(* Logix 5000 project; controller ControlLogix 1756-L63 rev 18.11; software revision 18.01 *)

TASK MainTask (continuous, watchdog 500 ms) : MainProgram

MODULES
   Local : 1756-L63 (ICP 0, rev 18.11)
      Local_ENBT : 1756-ENBT (ICP 3, Ethernet 105.102.0.155, rev 2.4)
         Remote_ENBT : 1756-ENBT (Ethernet 105.102.0.65, rev 1.1, Output RPI 20 ms)
            MCMR : vendor 1 type 0 code 15 (ICP 1, rev 1.1, Output RPI 5 ms)
END_MODULES

TYPE MCMRBlockStats :   // This object is used to store the block transfer statistics for the module.
STRUCT
   Read : INT;   // Total number of read block transfers
   Write : INT;   // Total number of write block transfers
   Parse : INT;   // Total number of blocks parsed
   Event : INT;   // Total number of event blocks received
   Cmd : INT;   // Total number of command blocks received
   Err : INT;   // Total number of block transfer errors
END_STRUCT
END_TYPE

TYPE MCMRCmdControl :   // Tags for command control
STRUCT
   CmdTrigger : BOOL;   // Command Trigger
   CmdControlData : INT[21];   // Command Control Data
   CmdControlResp : INT[5];   // Command Control Response
   CmdErrTrigger : BOOL;   // Command Error Trigger
   CmdErrData : INT[102];   // Command Error Data
END_STRUCT
END_TYPE

TYPE MCMRCONTROL :   // Tags used for special blocks
STRUCT
   ColdBoot : BOOL;   // Cold Boot
   WarmBoot : BOOL;   // Warm Boot
   CmdControlP1 : MCMRCmdControl;   // Command Control for Port 1
   CmdControlP2 : MCMRCmdControl;   // Command Control for Port 2
   EventTriggerP1 : BOOL;   // Triggers the Event Command.
   EventTriggerP2 : BOOL;   // Triggers the Event Command.
   EventCmdP1 : MCMREventCmd[100];   // Event Command for Port 1
   EventCmdP2 : MCMREventCmd[100];   // Event Command for Port 2
   EventCmdRespP1 : INT[5];   // Event Command Response for Port 1
   EventCmdRespP2 : INT[5];   // Event Command Response for Port 2
END_STRUCT
END_TYPE

TYPE MCMRDATA :   // This object contains the Read & Write Data Arrays.
STRUCT
   ReadData : INT[600];   // Data read from module
   WriteData : INT[600];   // Data to write to module
END_STRUCT
END_TYPE

TYPE MCMREventCmd :   // This object is used to contain the attributes to define a master command. An array of these objects is used for each port.
STRUCT
   Enable : INT;   // 0=Disable,1=Continuous,2=Event Command
   IntAddress : INT;   // Module's internal address associated with the command
   PollInt : INT;   // Minimum number of seconds between issuance of command (0-65535 Sec)
   Count : INT;   // Number of registers associated with the command
   Swap : INT;   // Swap code used with command
   Device : INT;   // Device index in Device Table to associate with the command
   Func : INT;   // Function code for the command
   DevAddress : INT;   // Address in device associated with the command
END_STRUCT
END_TYPE

TYPE MCMRInitOutputData :   // Used to bring the Module into a known state after a restart operation.
STRUCT
   InitOutBlkIDLim : INT;   // Block Index Limit for ReadData size of the array
END_STRUCT
END_TYPE

TYPE MCMRModuleDef :   // This object contains variables to be used with the module and status data related to the module.
STRUCT
   DATA : MCMRDATA;   // Read Data and Write Data
   STATUS : MCMRSTATUS;   // Status information in each read block
   CONTROL : MCMRCONTROL;   // Command Control Object
   UTIL : MCMRUTIL;   // Backplane Object
END_STRUCT
END_TYPE

TYPE MCMRPortStats :   // This object is used to store the port statistics
STRUCT
   PortTrigger : BOOL;   // Triggers port status reading
   CmdReq : INT;   // Total number of command list requests sent
   CmdResp : INT;   // Total number of command list responses received
   CmdErr : INT;   // Total number of command list errors
   Requests : INT;   // Total number of requests for port
   Responses : INT;   // Total number of responses for port
   ErrSent : INT;   // Total number of errors sent
   ErrRec : INT;   // Total number of errors received
   SlaveStats : SINT[250];   // Port Slave status values
END_STRUCT
END_TYPE

TYPE MCMRSTATUS :   // This status data is returned on each read block and can be used to detect proper module operation.
STRUCT
   PassCnt : INT;   // Program cycle counter
   Product : INT[2];   // Product Name
   Rev : INT[2];   // Revision Level Number
   OP : INT[2];   // Operating Level Number
   Run : INT[2];   // Run Number
   Port1Stats : MCMRPortStats;   // Port error statistics for Port 1
   Port2Stats : MCMRPortStats;   // Port error statistics for Port 2
   Block : MCMRBlockStats;   // Block transfer statistics
   Port1CurrentErr : INT;   // Current error/index for Port 1
   Port1LastErr : INT;   // Last error/index for Port 1
   Port2CurrentErr : INT;   // Current error/index for Port 2
   Port2LastErr : INT;   // Last error/index for Port 2
   StatusMsgData : INT[46];   // Triggers status message data
   StatusTrigger : BOOL;   // Triggers Status reading.
END_STRUCT
END_TYPE

TYPE MCMRUTIL :   // This object stores all the variables required for data transfer operation between the module and the controller.
STRUCT
   LastRead : INT;   // Index of last read block
   LastWrite : INT;   // Index of last write block
   BlockIndex : INT;   // Computed block offset for data table
   ReadDataSize : DINT;   // Size of Read Data Array
   WriteDataSize : DINT;   // Size of Write Data Array
   RBTSremainder : INT;   // Computed remainder from Read Data Array size
   WBTSremainder : INT;   // Computed remainder from Write Data Array size
   MaxReadBlock : DINT;   // Maximum read block
   MaxWriteBlock : DINT;   // Maximum write block
   InitOutputData : MCMRInitOutputData;   // This is to initialize output data module reads data from PLC
END_STRUCT
END_TYPE

ADD_ON_INSTRUCTION AOI56MCMR   (* revision 1.5, vendor ProSoft Technology Inc., ExecutePrescan *)
// Add-On - MVI56-MCMR & MVI56E-MCMR modules.
// Revision note:
// v1.5 - Initialize output data block now flexible to accommodate for flexible read and write data arrays.
VAR_IN_OUT
   Connection_Input : INT[42]; {required}   // Input parameters.
   Connection_Output : INT[42]; {required}   // Output parameters.
   MCMR : MCMRModuleDef; {required}
   CmdControlP1_MSG : MESSAGE; {required}
   CmdControlP2_MSG : MESSAGE; {required}
   CmdControlRespP1_MSG : MESSAGE; {required}
   CmdControlRespP2_MSG : MESSAGE; {required}
   CmdErrorP1_MSG : MESSAGE; {required}
   CmdErrorP2_MSG : MESSAGE; {required}
   EventCmdP1_MSG : MESSAGE; {required}
   EventCmdP2_MSG : MESSAGE; {required}
   EventCmdRespP1_MSG : MESSAGE; {required}
   EventCmdRespP2_MSG : MESSAGE; {required}
   SlaveStatusP1_MSG : MESSAGE; {required}
   SlaveStatusP2_MSG : MESSAGE; {required}
   ModuleStatus_MSG : MESSAGE; {required}
END_VAR
VAR
   MJFAULTS : DINT[12];
END_VAR

ROUTINE Logic   (* ladder *)
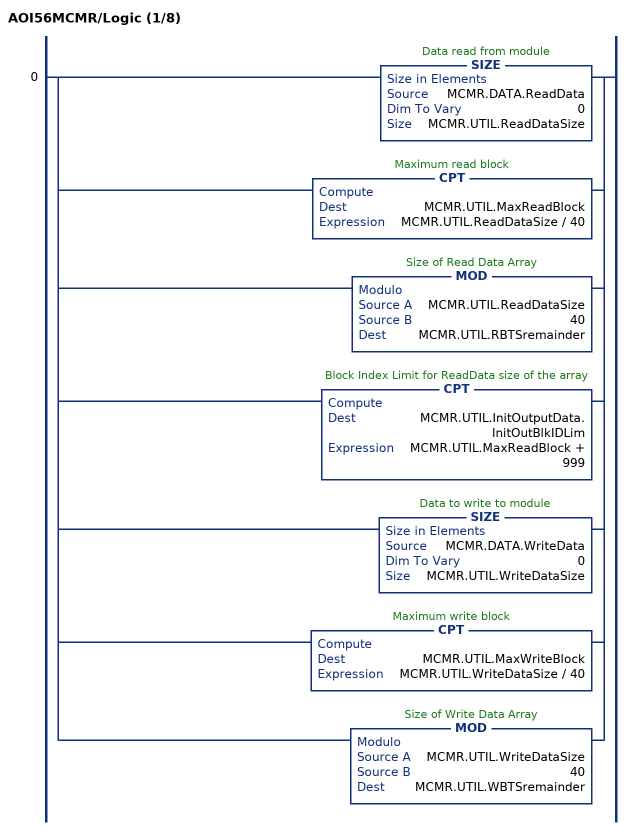
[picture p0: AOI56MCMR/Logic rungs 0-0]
   0: [SIZE(MCMR.DATA.ReadData,0,MCMR.UTIL.ReadDataSize) ,CPT(MCMR.UTIL.MaxReadBlock,MCMR.UTIL.ReadDataSize / 40) ,MOD(MCMR.UTIL.ReadDataSize,40,MCMR.UTIL.RBTSremainder) ,CPT(MCMR.UTIL.InitOutputData.InitOutBlkIDLim,MCMR.UTIL.MaxReadBlock + 999) ,SIZE(MCMR.DATA.WriteData,0,MCMR.UTIL.WriteDataSize) ,CPT(MCMR.UTIL.MaxWriteBlock,MCMR.UTIL.WriteDataSize / 40) ,MOD(MCMR.UTIL.WriteDataSize,40,MCMR.UTIL.WBTSremainder) ];
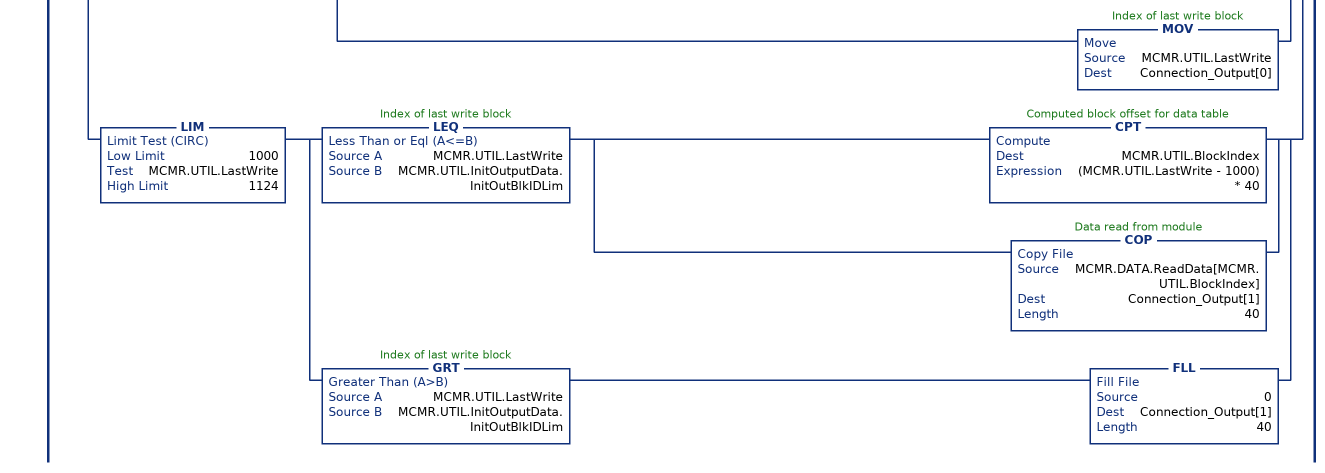
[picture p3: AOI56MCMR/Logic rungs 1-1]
   // This rung is used to check for a new read block from the MVI56-MBP module in slot 1.  If new data is available, the LastRead and word[0] will not be equal.  This will force the program to call the ReadData subroutine to process the new data received.  After the new data is placed in the Modbus Data Table, the program will send new data to the module using the WriteData subroutine.
   1: NEQ(Connection_Input[41],MCMR.UTIL.LastRead)[MOV(Connection_Input[41],MCMR.UTIL.LastRead) ,GEQ(MCMR.UTIL.LastRead,1) [LEQ(MCMR.UTIL.LastRead,MCMR.UTIL.MaxReadBlock) [CPT(MCMR.UTIL.BlockIndex,(MCMR.UTIL.LastRead - 1) * 40) ,COP(Connection_Input[1],MCMR.DATA.ReadData[MCMR.UTIL.BlockIndex],40) ] ,CMP(MCMR.UTIL.LastRead - MCMR.UTIL.MaxReadBlock = 1) GRT(MCMR.UTIL.RBTSremainder,0) [CPT(MCMR.UTIL.BlockIndex,(MCMR.UTIL.LastRead - 1) * 40) ,COP(Connection_Input[1],MCMR.DATA.ReadData[MCMR.UTIL.BlockIndex],MCMR.UTIL.RBTSremainder) ] ] ,MOV(Connection_Input[0],MCMR.UTIL.LastWrite) ,XIC(MCMR.CONTROL.WarmBoot) [MOV(9998,MCMR.UTIL.LastWrite) ,MOV(9998,Connection_Output[0]) ,OTU(MCMR.CONTROL.WarmBoot) ] ,XIC(MCMR.CONTROL.ColdBoot) [MOV(9999,MCMR.UTIL.LastWrite) ,MOV(9999,Connection_Output[0]) ,OTU(MCMR.CONTROL.ColdBoot) ] ,[EQU(-1,MCMR.UTIL.LastWrite) ,EQU(0,MCMR.UTIL.LastWrite) ] MOV(MCMR.UTIL.LastWrite,Connection_Output[0]) ,GEQ(MCMR.UTIL.LastWrite,1) [LEQ(MCMR.UTIL.LastWrite,MCMR.UTIL.MaxWriteBlock) [CPT(MCMR.UTIL.BlockIndex,(MCMR.UTIL.LastWrite - 1) * 40) ,COP(MCMR.DATA.WriteData[MCMR.UTIL.BlockIndex],Connection_Output[1],40) ] ,CMP(MCMR.UTIL.LastWrite - MCMR.UTIL.MaxWriteBlock = 1) GRT(MCMR.UTIL.WBTSremainder,0) [CPT(MCMR.UTIL.BlockIndex,(MCMR.UTIL.LastWrite - 1) * 40) ,COP(MCMR.DATA.WriteData[MCMR.UTIL.BlockIndex],Connection_Output[1],MCMR.UTIL.WBTSremainder) ] ,MOV(MCMR.UTIL.LastWrite,Connection_Output[0]) ] ,LIM(1000,MCMR.UTIL.LastWrite,1124) [LEQ(MCMR.UTIL.LastWrite,MCMR.UTIL.InitOutputData.InitOutBlkIDLim) [CPT(MCMR.UTIL.BlockIndex,(MCMR.UTIL.LastWrite - 1000) * 40) ,COP(MCMR.DATA.ReadData[MCMR.UTIL.BlockIndex],Connection_Output[1],40) ] ,GRT(MCMR.UTIL.LastWrite,MCMR.UTIL.InitOutputData.InitOutBlkIDLim) FLL(0,Connection_Output[1],40) ] ];
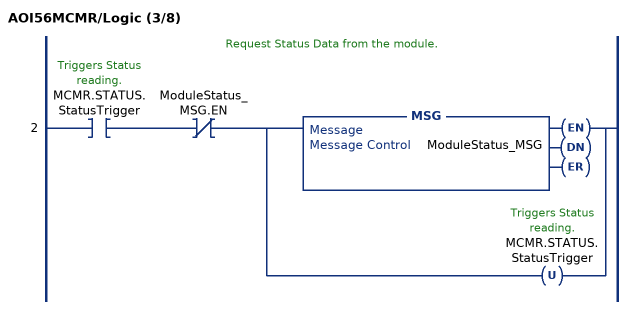
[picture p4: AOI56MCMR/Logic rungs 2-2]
   // Request Status Data from the module.
   2: XIC(MCMR.STATUS.StatusTrigger)XIO(ModuleStatus_MSG.EN)[MSG(ModuleStatus_MSG) ,OTU(MCMR.STATUS.StatusTrigger) ];
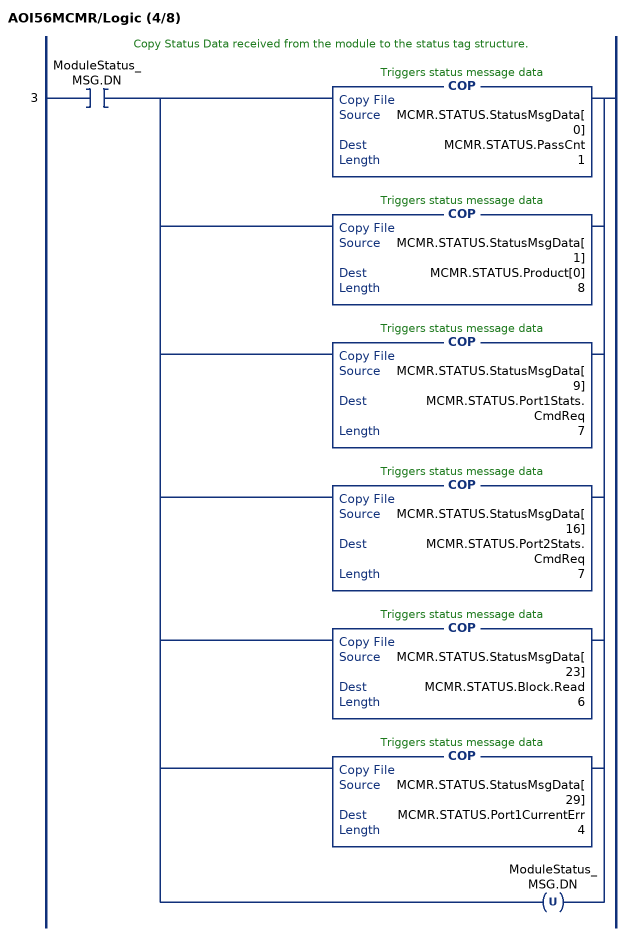
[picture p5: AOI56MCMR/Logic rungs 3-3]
   // Copy Status Data received from the module to the status tag structure.
   3: XIC(ModuleStatus_MSG.DN)[COP(MCMR.STATUS.StatusMsgData[0],MCMR.STATUS.PassCnt,1) ,COP(MCMR.STATUS.StatusMsgData[1],MCMR.STATUS.Product[0],8) ,COP(MCMR.STATUS.StatusMsgData[9],MCMR.STATUS.Port1Stats.CmdReq,7) ,COP(MCMR.STATUS.StatusMsgData[16],MCMR.STATUS.Port2Stats.CmdReq,7) ,COP(MCMR.STATUS.StatusMsgData[23],MCMR.STATUS.Block.Read,6) ,COP(MCMR.STATUS.StatusMsgData[29],MCMR.STATUS.Port1CurrentErr,4) ,OTU(ModuleStatus_MSG.DN) ];
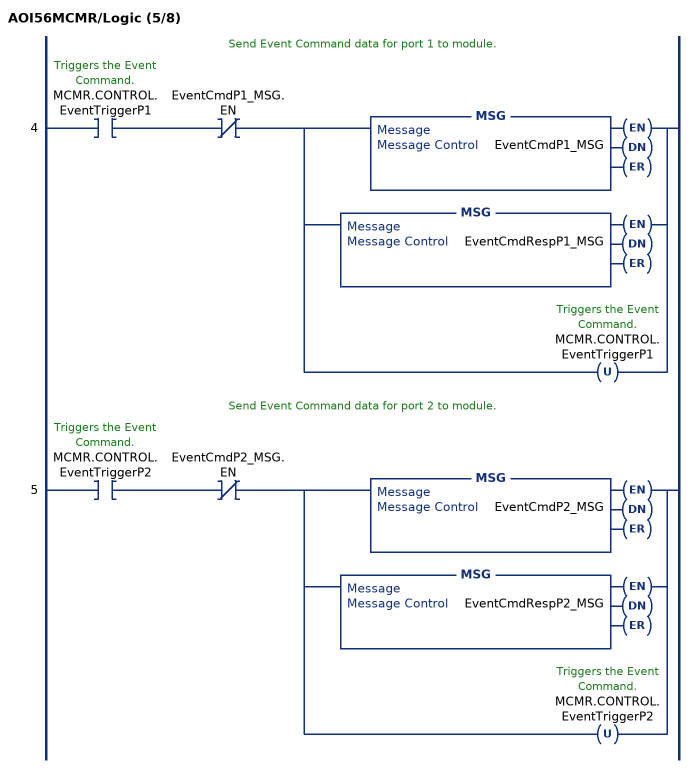
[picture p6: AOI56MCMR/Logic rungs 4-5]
   // Send Event Command data for port 1 to module.
   4: XIC(MCMR.CONTROL.EventTriggerP1)XIO(EventCmdP1_MSG.EN)[[MSG(EventCmdP1_MSG) ,MSG(EventCmdRespP1_MSG) ] ,OTU(MCMR.CONTROL.EventTriggerP1) ];
   // Send Event Command data for port 2 to module.
   5: XIC(MCMR.CONTROL.EventTriggerP2)XIO(EventCmdP2_MSG.EN)[[MSG(EventCmdP2_MSG) ,MSG(EventCmdRespP2_MSG) ] ,OTU(MCMR.CONTROL.EventTriggerP2) ];
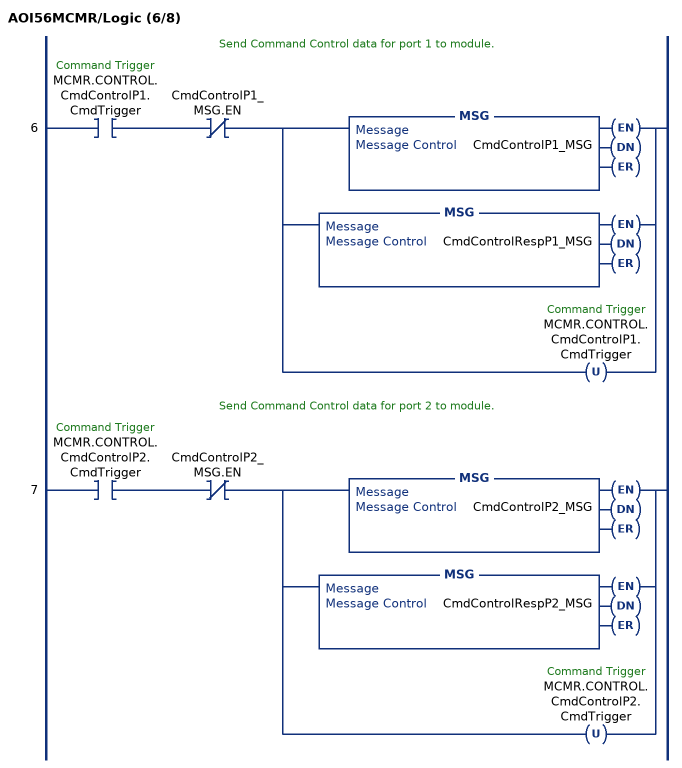
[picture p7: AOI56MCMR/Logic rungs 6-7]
   // Send Command Control data for port 1 to module.
   6: XIC(MCMR.CONTROL.CmdControlP1.CmdTrigger)XIO(CmdControlP1_MSG.EN)[[MSG(CmdControlP1_MSG) ,MSG(CmdControlRespP1_MSG) ] ,OTU(MCMR.CONTROL.CmdControlP1.CmdTrigger) ];
   // Send Command Control data for port 2 to module.
   7: XIC(MCMR.CONTROL.CmdControlP2.CmdTrigger)XIO(CmdControlP2_MSG.EN)[[MSG(CmdControlP2_MSG) ,MSG(CmdControlRespP2_MSG) ] ,OTU(MCMR.CONTROL.CmdControlP2.CmdTrigger) ];
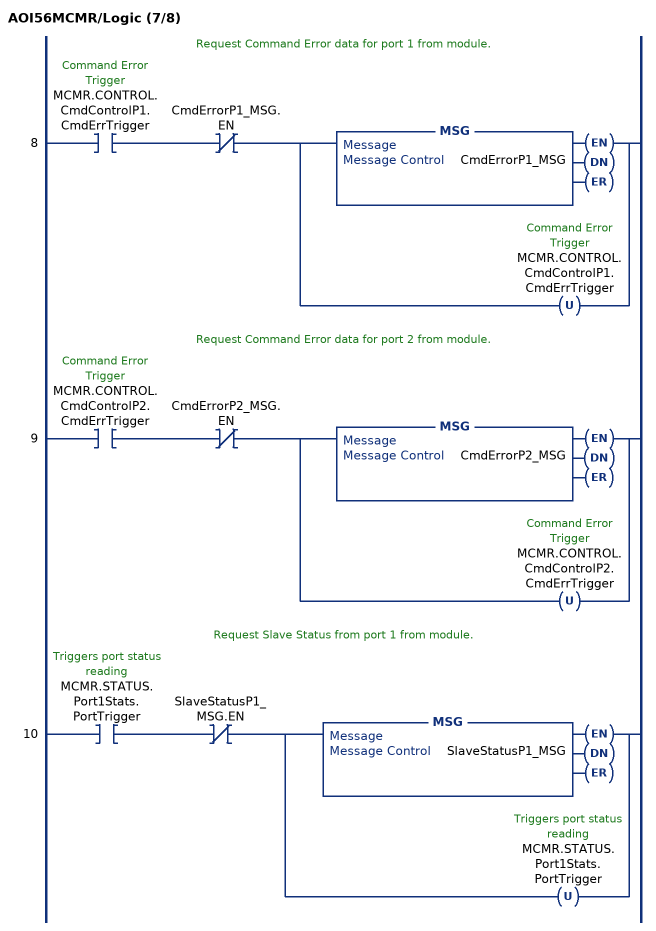
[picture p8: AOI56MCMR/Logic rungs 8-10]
   // Request Command Error data for port 1 from module.
   8: XIC(MCMR.CONTROL.CmdControlP1.CmdErrTrigger)XIO(CmdErrorP1_MSG.EN)[MSG(CmdErrorP1_MSG) ,OTU(MCMR.CONTROL.CmdControlP1.CmdErrTrigger) ];
   // Request Command Error data for port 2 from module.
   9: XIC(MCMR.CONTROL.CmdControlP2.CmdErrTrigger)XIO(CmdErrorP2_MSG.EN)[MSG(CmdErrorP2_MSG) ,OTU(MCMR.CONTROL.CmdControlP2.CmdErrTrigger) ];
   // Request Slave Status from port 1 from module.
   10: XIC(MCMR.STATUS.Port1Stats.PortTrigger)XIO(SlaveStatusP1_MSG.EN)[MSG(SlaveStatusP1_MSG) ,OTU(MCMR.STATUS.Port1Stats.PortTrigger) ];
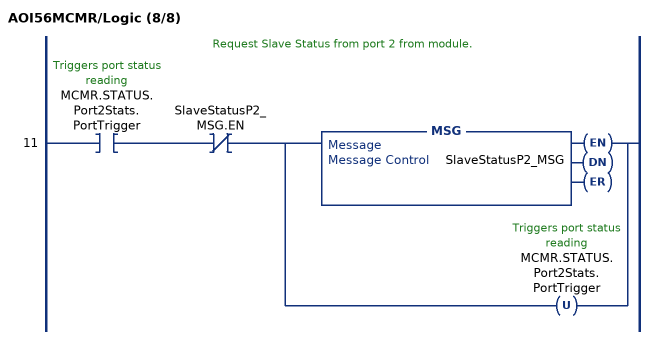
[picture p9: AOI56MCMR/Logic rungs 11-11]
   // Request Slave Status from port 2 from module.
   11: XIC(MCMR.STATUS.Port2Stats.PortTrigger)XIO(SlaveStatusP2_MSG.EN)[MSG(SlaveStatusP2_MSG) ,OTU(MCMR.STATUS.Port2Stats.PortTrigger) ];
END_ROUTINE

ROUTINE Prescan   (* ladder *)
// Startup
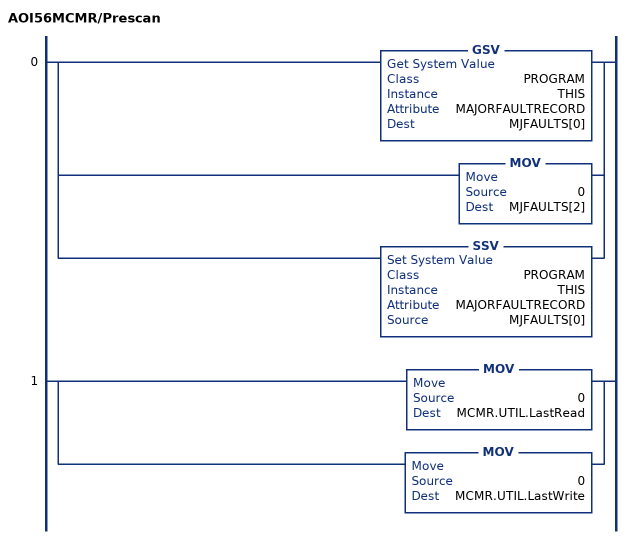
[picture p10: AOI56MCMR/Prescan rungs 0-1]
   0: [GSV(PROGRAM,THIS,MAJORFAULTRECORD,MJFAULTS[0]) ,MOV(0,MJFAULTS[2]) ,SSV(PROGRAM,THIS,MAJORFAULTRECORD,MJFAULTS[0]) ];
   1: [MOV(0,MCMR.UTIL.LastRead) ,MOV(0,MCMR.UTIL.LastWrite) ];
END_ROUTINE
END_ADD_ON_INSTRUCTION

VAR_GLOBAL   (* controller tags *)
   AOI56MCMR : AOI56MCMR;
   CmdControlP1_MSG : MESSAGE;
        MessageParameters(ServiceCode := 16#0010, LocalElement := MCMR.CONTROL.CmdControlP1.CmdControlData[0], ...)
   CmdControlP2_MSG : MESSAGE;
        MessageParameters(ServiceCode := 16#0010, LocalElement := MCMR.CONTROL.CmdControlP2.CmdControlData[0], ...)
   CmdControlRespP1_MSG : MESSAGE;
        MessageParameters(ServiceCode := 16#000e, DestinationTag := MCMR.CONTROL.CmdControlP1.CmdControlResp[0], ...)
   CmdControlRespP2_MSG : MESSAGE;
        MessageParameters(ServiceCode := 16#000e, DestinationTag := MCMR.CONTROL.CmdControlP2.CmdControlResp[0], ...)
   CmdErrorP1_MSG : MESSAGE;
        MessageParameters(ServiceCode := 16#000e, DestinationTag := MCMR.CONTROL.CmdControlP1.CmdErrData[0], ...)
   CmdErrorP2_MSG : MESSAGE;
        MessageParameters(ServiceCode := 16#000e, DestinationTag := MCMR.CONTROL.CmdControlP2.CmdErrData[0], ...)
   EventCmdP1_MSG : MESSAGE;
        MessageParameters(ServiceCode := 16#0010, LocalElement := MCMR.CONTROL.EventCmdP1[0], ...)
   EventCmdP2_MSG : MESSAGE;
        MessageParameters(ServiceCode := 16#0010, LocalElement := MCMR.CONTROL.EventCmdP2[0], ...)
   EventCmdRespP1_MSG : MESSAGE;
        MessageParameters(ServiceCode := 16#000e, DestinationTag := MCMR.CONTROL.EventCmdRespP1[0], ...)
   EventCmdRespP2_MSG : MESSAGE;
        MessageParameters(ServiceCode := 16#000e, DestinationTag := MCMR.CONTROL.EventCmdRespP2[0], ...)
   MCMR : MCMRModuleDef;
   ModuleStatus_MSG : MESSAGE;
        MessageParameters(ServiceCode := 16#000e, DestinationTag := MCMR.STATUS.StatusMsgData[0], ...)
   SlaveStatusP1_MSG : MESSAGE;
        MessageParameters(ServiceCode := 16#000e, DestinationTag := MCMR.STATUS.Port1Stats.SlaveStats[0], ...)
   SlaveStatusP2_MSG : MESSAGE;
        MessageParameters(ServiceCode := 16#000e, DestinationTag := MCMR.STATUS.Port2Stats.SlaveStats[0], ...)
END_VAR

PROGRAM MainProgram   (* main routine MainRoutine *)

ROUTINE MainRoutine   (* ladder *)
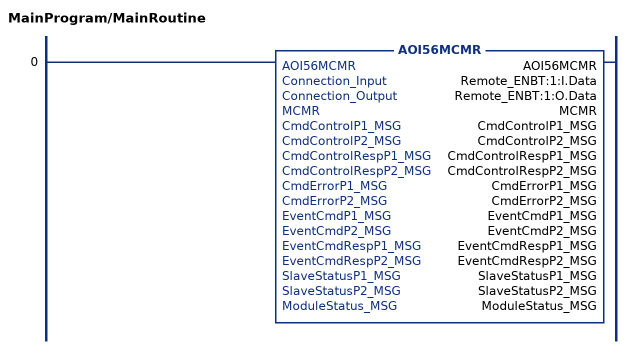
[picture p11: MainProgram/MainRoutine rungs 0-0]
   0: AOI56MCMR(AOI56MCMR,Remote_ENBT:1:I.Data,Remote_ENBT:1:O.Data,MCMR,CmdControlP1_MSG,CmdControlP2_MSG,CmdControlRespP1_MSG,CmdControlRespP2_MSG,CmdErrorP1_MSG,CmdErrorP2_MSG,EventCmdP1_MSG,EventCmdP2_MSG,EventCmdRespP1_MSG,EventCmdRespP2_MSG,SlaveStatusP1_MSG,SlaveStatusP2_MSG,ModuleStatus_MSG);
END_ROUTINE
END_PROGRAM
